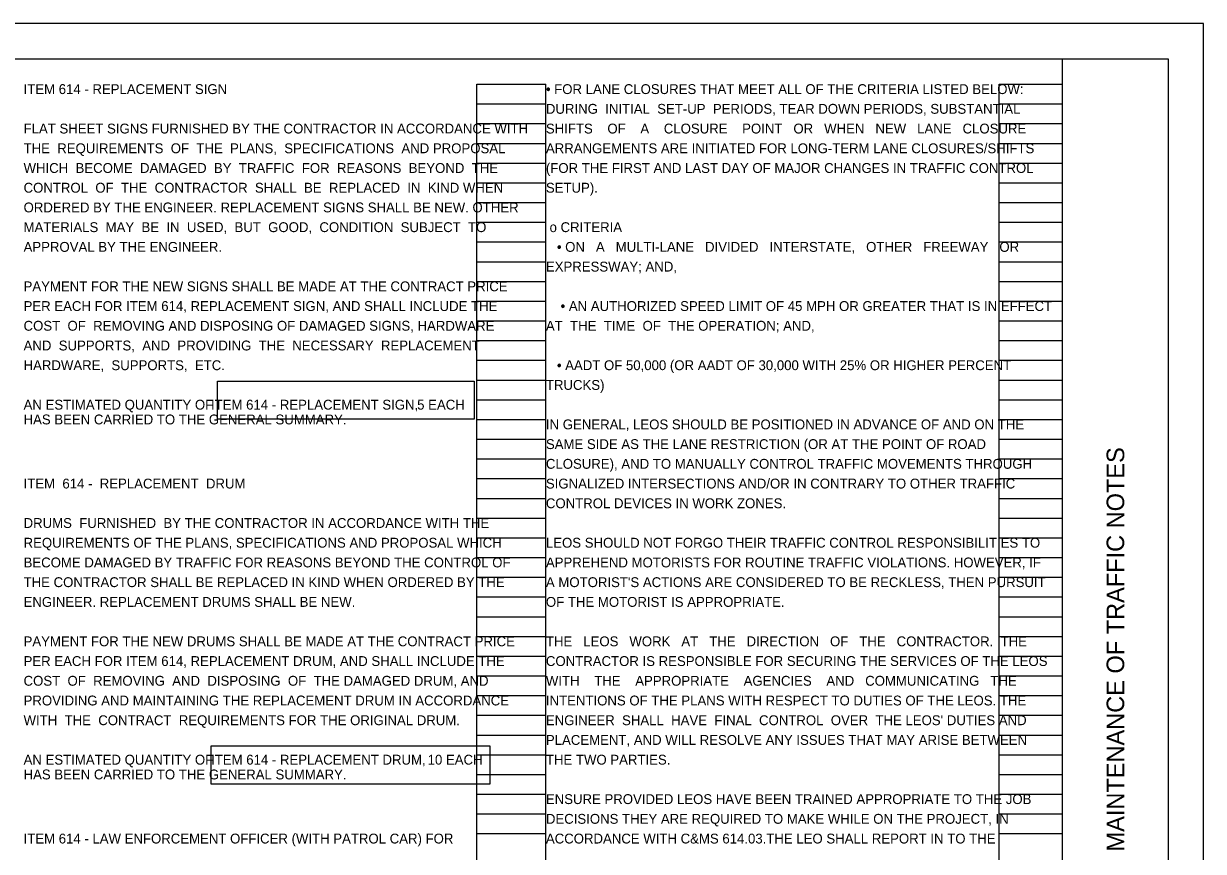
# Model space of a CAD drawing. Extents: x 0 to 34, y 0 to 22.
# Drawn here: x 17.24 to 34, y 10.25 to 22 of the extents above; entities that cross this region are included whole.
import ezdxf

# ---------------------------------------------------------------- set-up
doc = ezdxf.new("R2010")
doc.units = 0
for name, color, linetype in [('SC_Scratch1', 7, 'Continuous'), ('SH_Border', 7, 'Continuous'), ('SH_Cut_Line', 7, 'Continuous'), ('SH_Data', 7, 'Continuous'), ('SH_Text', 7, 'Continuous')]:
    doc.layers.add(name, color=color, linetype=linetype)

msp = doc.modelspace()

# ---------------------------------------------------------------- linework, layer by layer
at = {"layer": 'SC_Scratch1'}
for points in [[(19.993, 16.926), (23.641, 16.926), (23.641, 16.383), (19.993, 16.383)], [(19.907, 11.745), (23.861, 11.745), (23.861, 11.202), (19.907, 11.202)]]:
    msp.add_lwpolyline(points, close=True, dxfattribs=at)
at = {"layer": 'SH_Border'}
msp.add_line((32, 0.5), (32, 21.5), dxfattribs=at)
msp.add_lwpolyline([(1.5, 21.5), (33.5, 21.5), (33.5, 0.5), (1.5, 0.5)], close=True, dxfattribs=at)
at = {"layer": 'SH_Cut_Line'}
msp.add_lwpolyline([(0, 0), (34, 0), (34, 22), (0, 22)], close=True, dxfattribs=at)
at = {"layer": 'SH_Data'}
for p, q in [((23.68, 0.98), (23.68, 21.14)), ((23.68, 21.14), (24.66, 21.14)), ((24.66, 0.98), (24.66, 21.14)), ((31.1, 0.98), (31.1, 21.14)), ((31.1, 21.14), (32, 21.14)), ((32, 0.98), (32, 21.14)), ((23.68, 20.86), (24.66, 20.86)), ((31.1, 20.86), (32, 20.86)), ((23.68, 20.58), (24.66, 20.58)), ((31.1, 20.58), (32, 20.58)), ((23.68, 20.3), (24.66, 20.3)), ((31.1, 20.3), (32, 20.3)), ((23.68, 20.02), (24.66, 20.02)), ((31.1, 20.02), (32, 20.02)), ((23.68, 19.74), (24.66, 19.74)), ((31.1, 19.74), (32, 19.74)), ((23.68, 19.46), (24.66, 19.46)), ((31.1, 19.46), (32, 19.46)), ((23.68, 19.18), (24.66, 19.18)), ((31.1, 19.18), (32, 19.18)), ((23.68, 18.9), (24.66, 18.9)), ((31.1, 18.9), (32, 18.9)), ((23.68, 18.62), (24.66, 18.62)), ((31.1, 18.62), (32, 18.62)), ((23.68, 18.34), (24.66, 18.34)), ((31.1, 18.34), (32, 18.34)), ((23.68, 18.06), (24.66, 18.06)), ((31.1, 18.06), (32, 18.06)), ((23.68, 17.78), (24.66, 17.78)), ((31.1, 17.78), (32, 17.78)), ((23.68, 17.5), (24.66, 17.5)), ((31.1, 17.5), (32, 17.5)), ((23.68, 17.22), (24.66, 17.22)), ((31.1, 17.22), (32, 17.22)), ((23.68, 16.94), (24.66, 16.94)), ((31.1, 16.94), (32, 16.94)), ((23.68, 16.66), (24.66, 16.66)), ((31.1, 16.66), (32, 16.66)), ((23.68, 16.38), (24.66, 16.38)), ((31.1, 16.38), (32, 16.38)), ((23.68, 16.1), (24.66, 16.1)), ((31.1, 16.1), (32, 16.1)), ((23.68, 15.82), (24.66, 15.82)), ((31.1, 15.82), (32, 15.82)), ((23.68, 15.54), (24.66, 15.54)), ((31.1, 15.54), (32, 15.54)), ((23.68, 15.26), (24.66, 15.26)), ((31.1, 15.26), (32, 15.26)), ((23.68, 14.98), (24.66, 14.98)), ((31.1, 14.98), (32, 14.98)), ((23.68, 14.7), (24.66, 14.7)), ((31.1, 14.7), (32, 14.7)), ((23.68, 14.42), (24.66, 14.42)), ((31.1, 14.42), (32, 14.42)), ((23.68, 14.14), (24.66, 14.14)), ((31.1, 14.14), (32, 14.14)), ((23.68, 13.86), (24.66, 13.86)), ((31.1, 13.86), (32, 13.86)), ((23.68, 13.58), (24.66, 13.58)), ((31.1, 13.58), (32, 13.58)), ((23.68, 13.3), (24.66, 13.3)), ((31.1, 13.3), (32, 13.3)), ((23.68, 13.02), (24.66, 13.02)), ((31.1, 13.02), (32, 13.02)), ((23.68, 12.74), (24.66, 12.74)), ((31.1, 12.74), (32, 12.74)), ((23.68, 12.46), (24.66, 12.46)), ((31.1, 12.46), (32, 12.46)), ((23.68, 12.18), (24.66, 12.18)), ((31.1, 12.18), (32, 12.18)), ((23.68, 11.9), (24.66, 11.9)), ((31.1, 11.9), (32, 11.9)), ((23.68, 11.62), (24.66, 11.62)), ((31.1, 11.62), (32, 11.62)), ((23.68, 11.34), (24.66, 11.34)), ((31.1, 11.34), (32, 11.34)), ((23.68, 11.06), (24.66, 11.06)), ((31.1, 11.06), (32, 11.06)), ((23.68, 10.78), (24.66, 10.78)), ((31.1, 10.78), (32, 10.78)), ((23.68, 10.5), (24.66, 10.5)), ((31.1, 10.5), (32, 10.5))]:
    msp.add_line(p, q, dxfattribs=at)

# ---------------------------------------------------------------- texts
msp.add_text('MAINTENANCE OF TRAFFIC NOTES', height=0.25, rotation=90, dxfattribs=at).set_placement((32.875, 10.247))
at = {"layer": 'SH_Text'}
for s, p in [('ITEM 614 - REPLACEMENT SIGN', (17.24, 21)), ('• FOR LANE CLOSURES THAT MEET ALL OF THE CRITERIA LISTED BELOW:', (24.66, 21)), ('DURING  INITIAL  SET-UP  PERIODS, TEAR DOWN PERIODS, SUBSTANTIAL', (24.66, 20.72)), ('FLAT SHEET SIGNS FURNISHED BY THE CONTRACTOR IN ACCORDANCE WITH', (17.24, 20.44)), ('SHIFTS    OF    A    CLOSURE    POINT   OR   WHEN   NEW   LANE   CLOSURE', (24.66, 20.44)), ('THE  REQUIREMENTS  OF  THE  PLANS,  SPECIFICATIONS  AND PROPOSAL', (17.24, 20.16)), ('ARRANGEMENTS ARE INITIATED FOR LONG-TERM LANE CLOSURES/SHIFTS', (24.66, 20.16)), ('WHICH  BECOME  DAMAGED  BY  TRAFFIC  FOR  REASONS  BEYOND  THE', (17.24, 19.88)), ('(FOR THE FIRST AND LAST DAY OF MAJOR CHANGES IN TRAFFIC CONTROL', (24.66, 19.88)), ('CONTROL  OF  THE  CONTRACTOR  SHALL  BE  REPLACED  IN  KIND WHEN', (17.24, 19.6)), ('SETUP).', (24.66, 19.6)), ('ORDERED BY THE ENGINEER. REPLACEMENT SIGNS SHALL BE NEW. OTHER', (17.24, 19.32)), ('MATERIALS  MAY  BE  IN  USED,  BUT  GOOD,  CONDITION  SUBJECT  TO', (17.24, 19.04)), (' o CRITERIA', (24.66, 19.04)), ('APPROVAL BY THE ENGINEER.', (17.24, 18.76)), ('   • ON   A   MULTI-LANE   DIVIDED   INTERSTATE,   OTHER   FREEWAY   OR', (24.66, 18.76)), ('EXPRESSWAY; AND,', (24.66, 18.48)), ('PAYMENT FOR THE NEW SIGNS SHALL BE MADE AT THE CONTRACT PRICE', (17.24, 18.2)), ('PER EACH FOR ITEM 614, REPLACEMENT SIGN, AND SHALL INCLUDE THE', (17.24, 17.92)), ('    • AN AUTHORIZED SPEED LIMIT OF 45 MPH OR GREATER THAT IS IN EFFECT', (24.66, 17.92)), ('COST  OF  REMOVING AND DISPOSING OF DAMAGED SIGNS, HARDWARE', (17.24, 17.64)), ('AT  THE  TIME  OF  THE OPERATION; AND,', (24.66, 17.64)), ('AND  SUPPORTS,  AND  PROVIDING  THE  NECESSARY  REPLACEMENT', (17.24, 17.36)), ('HARDWARE,  SUPPORTS,  ETC.', (17.24, 17.08)), ('   • AADT OF 50,000 (OR AADT OF 30,000 WITH 25% OR HIGHER PERCENT', (24.66, 17.08)), ('TRUCKS)', (24.66, 16.8)), ('AN ESTIMATED QUANTITY OF ', (17.24, 16.52)), ('ITEM 614 - REPLACEMENT SIGN, ', (19.902, 16.52)), ('5 EACH', (22.831, 16.52)), ('HAS BEEN CARRIED TO THE GENERAL SUMMARY.', (17.24, 16.31)), ('IN GENERAL, LEOS SHOULD BE POSITIONED IN ADVANCE OF AND ON THE', (24.66, 16.24)), ('SAME SIDE AS THE LANE RESTRICTION (OR AT THE POINT OF ROAD', (24.66, 15.96)), ('CLOSURE), AND TO MANUALLY CONTROL TRAFFIC MOVEMENTS THROUGH', (24.66, 15.68)), ('ITEM  614 -  REPLACEMENT  DRUM', (17.24, 15.4)), ('SIGNALIZED INTERSECTIONS AND/OR IN CONTRARY TO OTHER TRAFFIC', (24.66, 15.4)), ('CONTROL DEVICES IN WORK ZONES.', (24.66, 15.12)), ('DRUMS  FURNISHED  BY THE CONTRACTOR IN ACCORDANCE WITH THE', (17.24, 14.84)), ('REQUIREMENTS OF THE PLANS, SPECIFICATIONS AND PROPOSAL WHICH', (17.24, 14.56)), ('LEOS SHOULD NOT FORGO THEIR TRAFFIC CONTROL RESPONSIBILITIES TO', (24.66, 14.56)), ('BECOME DAMAGED BY TRAFFIC FOR REASONS BEYOND THE CONTROL OF', (17.24, 14.28)), ('APPREHEND MOTORISTS FOR ROUTINE TRAFFIC VIOLATIONS. HOWEVER, IF', (24.66, 14.28)), ('THE CONTRACTOR SHALL BE REPLACED IN KIND WHEN ORDERED BY THE', (17.24, 14)), ("A MOTORIST'S ACTIONS ARE CONSIDERED TO BE RECKLESS, THEN PURSUIT", (24.66, 14)), ('ENGINEER. REPLACEMENT DRUMS SHALL BE NEW.', (17.24, 13.72)), ('OF THE MOTORIST IS APPROPRIATE.', (24.66, 13.72)), ('PAYMENT FOR THE NEW DRUMS SHALL BE MADE AT THE CONTRACT PRICE', (17.24, 13.16)), ('THE   LEOS   WORK   AT   THE   DIRECTION   OF   THE   CONTRACTOR.  THE', (24.66, 13.16)), ('PER EACH FOR ITEM 614, REPLACEMENT DRUM, AND SHALL INCLUDE THE', (17.24, 12.88)), ('CONTRACTOR IS RESPONSIBLE FOR SECURING THE SERVICES OF THE LEOS', (24.66, 12.88)), ('COST  OF  REMOVING  AND  DISPOSING  OF  THE DAMAGED DRUM, AND', (17.24, 12.6)), ('WITH    THE    APPROPRIATE    AGENCIES    AND   COMMUNICATING   THE', (24.66, 12.6)), ('PROVIDING AND MAINTAINING THE REPLACEMENT DRUM IN ACCORDANCE', (17.24, 12.32)), ('INTENTIONS OF THE PLANS WITH RESPECT TO DUTIES OF THE LEOS. THE', (24.66, 12.32)), ('WITH  THE  CONTRACT  REQUIREMENTS FOR THE ORIGINAL DRUM.', (17.24, 12.04)), ("ENGINEER  SHALL  HAVE  FINAL  CONTROL  OVER  THE LEOS' DUTIES AND", (24.66, 12.04)), ('PLACEMENT, AND WILL RESOLVE ANY ISSUES THAT MAY ARISE BETWEEN', (24.66, 11.76)), ('AN ESTIMATED QUANTITY OF', (17.24, 11.48)), (' ITEM 614 - REPLACEMENT DRUM, ', (19.852, 11.48)), ('10 EACH', (22.98, 11.48)), ('THE TWO PARTIES.', (24.66, 11.48)), ('HAS BEEN CARRIED TO THE GENERAL SUMMARY.', (17.24, 11.27)), ('ENSURE PROVIDED LEOS HAVE BEEN TRAINED APPROPRIATE TO THE JOB', (24.66, 10.92)), ('DECISIONS THEY ARE REQUIRED TO MAKE WHILE ON THE PROJECT, IN', (24.66, 10.64)), ('ITEM 614 - LAW ENFORCEMENT OFFICER (WITH PATROL CAR) FOR', (17.24, 10.36)), ('ACCORDANCE WITH C&MS 614.03.THE LEO SHALL REPORT IN TO THE', (24.66, 10.36))]:
    msp.add_text(s, height=0.14, dxfattribs=at).set_placement(p)

doc.saveas('drawing.dxf')
